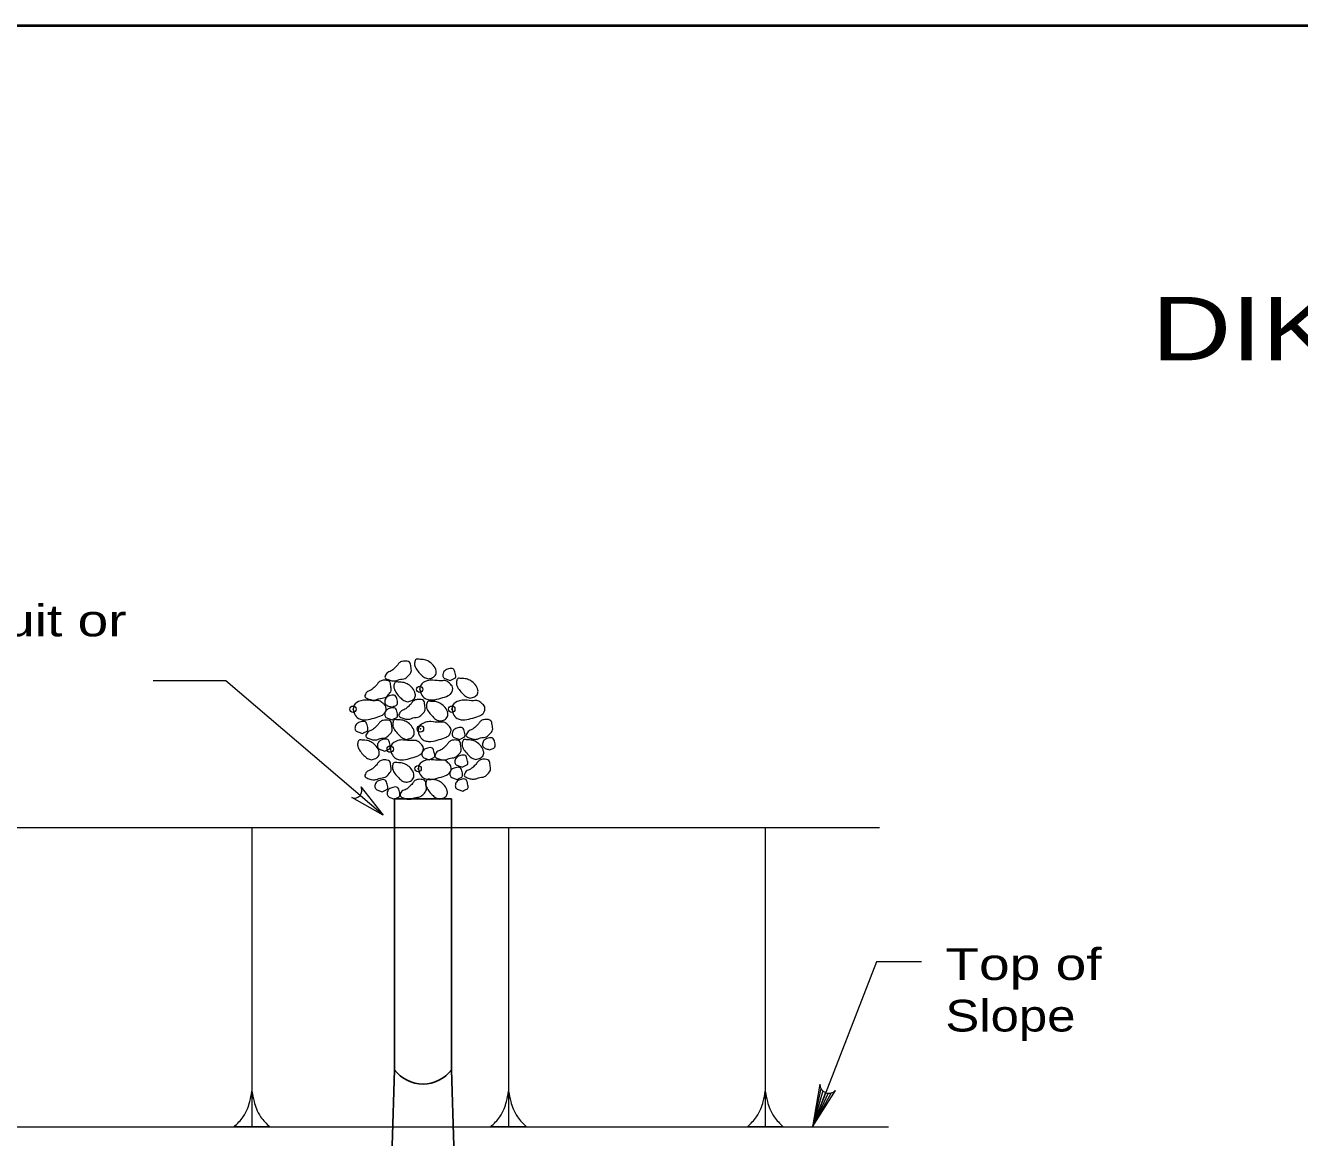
# Model space of a CAD drawing. Extents: x 1043.1 to 1101.1, y 672.4 to 716.4.
# Drawn here: x 1050.72 to 1057.15, y 688.26 to 693.9 of the extents above; entities that cross this region are included whole.
import ezdxf
from ezdxf.enums import TextEntityAlignment as Align

# ---------------------------------------------------------------- set-up
doc = ezdxf.new("R2010")
doc.units = 0
doc.header["$LTSCALE"] = 0.064
doc.header["$PDMODE"] = 32
doc.header["$PDSIZE"] = 0.032
doc.linetypes.add('LONG_DASHED', pattern=[7.5, 6, -1.5])
doc.layers.add('1', color=7, linetype='Continuous', lineweight=13)

msp = doc.modelspace()

# ---------------------------------------------------------------- linework, layer by layer
at = {"layer": '1', "lineweight": 25}
for p, q in [((1045.14425, 693.89508), (1076.64425, 693.89508)), ((1052.87325, 689.992), (1052.87325, 688.62467))]:
    msp.add_line(p, q, dxfattribs=at)
at = {"layer": '1', "lineweight": 40}
msp.add_line((1045.14425, 693.89508), (1076.64425, 693.89508), dxfattribs=at)
msp.add_line((1045.14425, 693.89508), (1076.64425, 693.89508), dxfattribs=at)
at = {"layer": '1'}
for p, q in [((1047.11617, 689.848), (1055.03217, 689.848)), ((1051.86575, 689.848), (1051.86575, 688.33692)), ((1053.16117, 689.848), (1053.16117, 688.33692)), ((1054.4565, 689.848), (1054.4565, 688.33692)), ((1054.73675, 688.53025), (1054.69375, 688.33692)), ((1054.74583, 688.51883), (1054.69375, 688.33692)), ((1054.76075, 688.50933), (1054.69375, 688.33692)), ((1054.78908, 688.5075), (1054.69375, 688.33692)), ((1054.77425, 688.50625), (1054.69375, 688.33692)), ((1054.75833, 688.50317), (1054.69475, 688.33942)), ((1047.11617, 688.33692), (1055.0785, 688.33692)), ((1051.95575, 688.33692), (1051.77583, 688.33692)), ((1053.25117, 688.33692), (1053.07117, 688.33692)), ((1054.5465, 688.33692), (1054.3665, 688.33692))]:
    msp.add_line(p, q, dxfattribs=at)
at = {"layer": '1', "linetype": 'LONG_DASHED', "lineweight": 25}
for p, q in [((1052.58533, 688.62467), (1052.55375, 687.54417)), ((1052.87325, 688.62467), (1052.905, 687.54417))]:
    msp.add_line(p, q, dxfattribs=at)
at = {"layer": '1'}
for points in [[(1052.528, 689.91042), (1051.73442, 690.58742), (1051.36792, 690.58742)], [(1052.41658, 690.05175), (1052.528, 689.91042), (1052.37075, 689.99808), (1052.37083, 689.99817)], [(1055.24533, 689.169), (1055.01717, 689.169), (1054.69375, 688.33692)], [(1054.73133, 688.55167), (1054.69375, 688.33692), (1054.811, 688.52067)]]:
    msp.add_lwpolyline(points, dxfattribs=at)
at = {"layer": '1', "lineweight": 25}
msp.add_lwpolyline([(1052.58533, 688.62467), (1052.58533, 689.992), (1052.87325, 689.992)], dxfattribs=at)
at = {"layer": '1'}
for centre, radius, start, end in [((1052.38283, 690.03431), 0.03811, 251.62064, 27.44677), ((1054.77748, 688.55222), 0.04613, 180.84579, 316.67192)]:
    msp.add_arc(centre, radius, start, end, dxfattribs=at)
at = {"layer": '1', "lineweight": 25}
msp.add_ellipse((1052.72935, 688.73267), major_axis=(-0.17991, 0), ratio=0.999895, start_param=0.6435011, end_param=2.4980916, dxfattribs=at)
at = {"layer": '1'}
for points in [[(1052.75592, 690.59767), (1052.73742, 690.60392), (1052.7185, 690.61925), (1052.69983, 690.64108), (1052.68783, 690.664), (1052.6875, 690.6815), (1052.69433, 690.69608), (1052.7095, 690.69667), (1052.73742, 690.69408), (1052.75917, 690.68467), (1052.78083, 690.66592), (1052.79517, 690.63775), (1052.79342, 690.61925), (1052.77792, 690.60392), (1052.75592, 690.59767)], [(1052.5715, 690.58792), (1052.55275, 690.594), (1052.53717, 690.60642), (1052.54017, 690.61558), (1052.54683, 690.62692), (1052.56833, 690.63725), (1052.58375, 690.64992), (1052.59933, 690.6655), (1052.60867, 690.67775), (1052.6245, 690.68592), (1052.64925, 690.68625), (1052.66183, 690.681), (1052.66792, 690.65925), (1052.67025, 690.63467), (1052.65492, 690.61292), (1052.63975, 690.60008), (1052.60867, 690.594), (1052.59317, 690.58792), (1052.5715, 690.58792)], [(1052.8665, 690.58917), (1052.848, 690.59525), (1052.83242, 690.60467), (1052.82925, 690.62017), (1052.8385, 690.63867), (1052.85775, 690.648), (1052.882, 690.64767), (1052.89133, 690.62625), (1052.89242, 690.60308), (1052.87917, 690.59525), (1052.8665, 690.58917)], [(1052.8665, 690.58917), (1052.848, 690.59525), (1052.83242, 690.60467), (1052.82925, 690.62017), (1052.8385, 690.63867), (1052.85775, 690.648), (1052.882, 690.64767), (1052.89133, 690.62625), (1052.89242, 690.60308), (1052.87917, 690.59525), (1052.8665, 690.58917)], [(1052.46975, 690.49125), (1052.45083, 690.49742), (1052.43525, 690.50975), (1052.43825, 690.51908), (1052.44492, 690.53042), (1052.46642, 690.54092), (1052.48192, 690.5535), (1052.4975, 690.56908), (1052.50692, 690.58125), (1052.52275, 690.5895), (1052.54742, 690.58975), (1052.56, 690.5845), (1052.56617, 690.56275), (1052.56833, 690.53817), (1052.55325, 690.51625), (1052.53792, 690.5035), (1052.50692, 690.49742), (1052.49142, 690.49125), (1052.46975, 690.49125)], [(1052.65117, 690.48208), (1052.63267, 690.48817), (1052.61383, 690.50375), (1052.59517, 690.5255), (1052.58317, 690.54842), (1052.58275, 690.56592), (1052.5895, 690.58058), (1052.60483, 690.58117), (1052.63267, 690.5785), (1052.65433, 690.56917), (1052.67617, 690.55025), (1052.69033, 690.52225), (1052.68875, 690.50375), (1052.67325, 690.48817), (1052.65117, 690.48208)], [(1052.75983, 690.4915), (1052.73942, 690.49867), (1052.71967, 690.52242), (1052.71675, 690.56317), (1052.75083, 690.58775), (1052.77875, 690.59075), (1052.82225, 690.58775), (1052.84392, 690.58775), (1052.86283, 690.57517), (1052.87833, 690.55625), (1052.8715, 690.52467), (1052.8565, 690.513), (1052.819, 690.50025), (1052.77875, 690.49125), (1052.75983, 690.4915)], [(1052.96683, 690.5005), (1052.94833, 690.50667), (1052.9295, 690.52225), (1052.91083, 690.544), (1052.89883, 690.56692), (1052.89842, 690.58442), (1052.90533, 690.59908), (1052.9205, 690.59967), (1052.94833, 690.597), (1052.97017, 690.58767), (1052.99183, 690.56875), (1053.00617, 690.54067), (1053.00442, 690.52225), (1052.98892, 690.50667), (1052.96683, 690.5005)], [(1052.57325, 690.45425), (1052.55492, 690.4605), (1052.53933, 690.46975), (1052.536, 690.48542), (1052.54542, 690.50392), (1052.56467, 690.51325), (1052.58875, 690.51292), (1052.59817, 690.4915), (1052.59917, 690.46825), (1052.58583, 690.4605), (1052.57325, 690.45425)], [(1052.42367, 690.391), (1052.40325, 690.39817), (1052.38342, 690.42167), (1052.3805, 690.4625), (1052.41467, 690.48708), (1052.44242, 690.49008), (1052.48617, 690.48708), (1052.50783, 690.48708), (1052.52675, 690.4745), (1052.54217, 690.45567), (1052.53542, 690.424), (1052.52042, 690.4125), (1052.48292, 690.39967), (1052.44242, 690.39067), (1052.42367, 690.391)], [(1052.57325, 690.39067), (1052.55492, 690.39692), (1052.53933, 690.40617), (1052.536, 690.42167), (1052.54542, 690.44017), (1052.56467, 690.4495), (1052.58875, 690.44917), (1052.59817, 690.42775), (1052.59917, 690.40467), (1052.58583, 690.39692), (1052.57325, 690.39067)], [(1052.64142, 690.3945), (1052.6225, 690.40058), (1052.60692, 690.41292), (1052.60992, 690.42217), (1052.61675, 690.4335), (1052.63817, 690.44392), (1052.65367, 690.4565), (1052.66925, 690.47208), (1052.67867, 690.48425), (1052.69442, 690.4925), (1052.71917, 690.49292), (1052.73175, 690.48758), (1052.73792, 690.46592), (1052.74017, 690.44125), (1052.72492, 690.41942), (1052.70975, 690.40667), (1052.67867, 690.40058), (1052.66317, 690.3945), (1052.64142, 690.3945)], [(1052.8155, 690.38508), (1052.797, 690.39117), (1052.77825, 690.40675), (1052.7595, 690.42842), (1052.7475, 690.45125), (1052.74717, 690.46892), (1052.75392, 690.4835), (1052.76925, 690.48408), (1052.797, 690.4815), (1052.81867, 690.47208), (1052.84033, 690.45325), (1052.85467, 690.42517), (1052.85292, 690.40675), (1052.8375, 690.39117), (1052.8155, 690.38508)], [(1052.92183, 690.391), (1052.90142, 690.39817), (1052.88167, 690.42167), (1052.87875, 690.4625), (1052.91283, 690.48708), (1052.94075, 690.49008), (1052.98433, 690.48708), (1053.00617, 690.48708), (1053.02492, 690.4745), (1053.04042, 690.45567), (1053.03375, 690.424), (1053.01875, 690.4125), (1052.98117, 690.39967), (1052.94075, 690.39067), (1052.92183, 690.391)], [(1052.4235, 690.32167), (1052.405, 690.32792), (1052.38942, 690.33717), (1052.38617, 690.35275), (1052.3955, 690.37125), (1052.41475, 690.38067), (1052.43892, 690.38025), (1052.44833, 690.35892), (1052.44942, 690.33567), (1052.43617, 690.32792), (1052.4235, 690.32167)], [(1052.47517, 690.29008), (1052.45625, 690.29617), (1052.44067, 690.3085), (1052.44367, 690.31792), (1052.45033, 690.32917), (1052.47183, 690.33958), (1052.48733, 690.35217), (1052.50292, 690.36775), (1052.51233, 690.38008), (1052.52817, 690.38817), (1052.55283, 690.38858), (1052.56542, 690.38325), (1052.5715, 690.36158), (1052.57383, 690.337), (1052.55867, 690.315), (1052.54333, 690.30225), (1052.51233, 690.29617), (1052.49683, 690.29008), (1052.47517, 690.29008)], [(1052.6455, 690.29192), (1052.627, 690.298), (1052.60817, 690.31358), (1052.58942, 690.33525), (1052.57742, 690.35817), (1052.57717, 690.37567), (1052.58392, 690.39042), (1052.59917, 690.391), (1052.627, 690.38825), (1052.64875, 690.379), (1052.67042, 690.36008), (1052.68475, 690.33208), (1052.683, 690.31358), (1052.6675, 690.298), (1052.6455, 690.29192)], [(1052.75075, 690.28225), (1052.73033, 690.2895), (1052.7105, 690.31308), (1052.70767, 690.35392), (1052.74175, 690.3785), (1052.7695, 690.3815), (1052.81325, 690.3785), (1052.83483, 690.3785), (1052.85375, 690.36592), (1052.86917, 690.34708), (1052.86242, 690.31542), (1052.84742, 690.30367), (1052.81, 690.291), (1052.7695, 690.282), (1052.75075, 690.28225)], [(1052.98167, 690.29325), (1052.96275, 690.29942), (1052.94717, 690.31175), (1052.95017, 690.32108), (1052.95692, 690.33242), (1052.97833, 690.34292), (1052.99383, 690.3555), (1053.00942, 690.37108), (1053.01883, 690.38325), (1053.03467, 690.3915), (1053.05933, 690.39175), (1053.07183, 690.3865), (1053.07792, 690.36475), (1053.08025, 690.34017), (1053.065, 690.31825), (1053.04992, 690.3055), (1053.01883, 690.29942), (1053.00333, 690.29325), (1052.98167, 690.29325)], [(1052.91342, 690.29142), (1052.89492, 690.2975), (1052.87933, 690.30692), (1052.87617, 690.3225), (1052.8855, 690.34092), (1052.90475, 690.35025), (1052.92892, 690.34992), (1052.93833, 690.32858), (1052.93933, 690.30525), (1052.926, 690.2975), (1052.91342, 690.29142)], [(1052.46833, 690.1895), (1052.44992, 690.19558), (1052.431, 690.21117), (1052.41233, 690.23275), (1052.40033, 690.25567), (1052.39992, 690.27325), (1052.40683, 690.28792), (1052.422, 690.2885), (1052.44992, 690.28592), (1052.47167, 690.2765), (1052.49333, 690.25767), (1052.50767, 690.22958), (1052.50592, 690.21117), (1052.49042, 690.19558), (1052.46833, 690.1895)], [(1052.5365, 690.2325), (1052.518, 690.23858), (1052.50242, 690.24792), (1052.49925, 690.2635), (1052.5085, 690.282), (1052.52775, 690.29142), (1052.552, 690.291), (1052.56133, 690.26967), (1052.56242, 690.24642), (1052.54917, 690.23858), (1052.5365, 690.2325)], [(1052.611, 690.18967), (1052.59067, 690.19692), (1052.57083, 690.2205), (1052.56817, 690.26125), (1052.602, 690.28592), (1052.62992, 690.28892), (1052.6735, 690.28592), (1052.69533, 690.28592), (1052.71417, 690.27325), (1052.72967, 690.25442), (1052.72292, 690.22267), (1052.70792, 690.21117), (1052.67033, 690.1985), (1052.62992, 690.1895), (1052.611, 690.18967)], [(1052.76083, 690.1895), (1052.74233, 690.19558), (1052.72675, 690.20492), (1052.7235, 690.2205), (1052.73283, 690.23892), (1052.752, 690.24825), (1052.77633, 690.24792), (1052.78567, 690.22658), (1052.78675, 690.20342), (1052.77342, 690.19558), (1052.76083, 690.1895)], [(1052.82325, 690.1895), (1052.8045, 690.19558), (1052.78892, 690.208), (1052.79192, 690.21717), (1052.79867, 690.2285), (1052.81992, 690.23892), (1052.83542, 690.2515), (1052.851, 690.26708), (1052.86042, 690.27942), (1052.87625, 690.2875), (1052.90092, 690.28792), (1052.9135, 690.28258), (1052.91975, 690.26092), (1052.92192, 690.23625), (1052.90675, 690.2145), (1052.8915, 690.20167), (1052.86042, 690.19558), (1052.84492, 690.1895), (1052.82325, 690.1895)], [(1052.9955, 690.19125), (1052.977, 690.19742), (1052.95825, 690.213), (1052.9395, 690.23458), (1052.9275, 690.2575), (1052.92717, 690.27508), (1052.93392, 690.28967), (1052.94925, 690.29025), (1052.977, 690.28767), (1052.99875, 690.27825), (1053.0205, 690.2595), (1053.03475, 690.23142), (1053.03317, 690.213), (1053.01767, 690.19742), (1052.9955, 690.19125)], [(1053.06633, 690.23908), (1053.04792, 690.24517), (1053.03233, 690.2545), (1053.02917, 690.27008), (1053.0385, 690.28858), (1053.0575, 690.298), (1053.08183, 690.29758), (1053.09117, 690.27625), (1053.09225, 690.253), (1053.07892, 690.24517), (1053.06633, 690.23908)], [(1052.46975, 690.08892), (1052.45083, 690.09508), (1052.43525, 690.10742), (1052.43825, 690.11675), (1052.44492, 690.12808), (1052.46642, 690.1385), (1052.48192, 690.15108), (1052.4975, 690.16667), (1052.50692, 690.17892), (1052.52275, 690.18708), (1052.54742, 690.1875), (1052.56, 690.18217), (1052.56617, 690.1605), (1052.56833, 690.13592), (1052.55325, 690.11392), (1052.53792, 690.10117), (1052.50692, 690.09508), (1052.49142, 690.08892), (1052.46975, 690.08892)], [(1052.75183, 690.0905), (1052.73142, 690.09767), (1052.71167, 690.12125), (1052.70875, 690.16208), (1052.74283, 690.18667), (1052.77067, 690.18967), (1052.81425, 690.18667), (1052.83592, 690.18667), (1052.85475, 690.17408), (1052.87025, 690.15525), (1052.8635, 690.12358), (1052.8485, 690.112), (1052.81092, 690.09925), (1052.77067, 690.09025), (1052.75183, 690.0905)], [(1052.92733, 690.15208), (1052.90892, 690.15817), (1052.89333, 690.1675), (1052.89, 690.18308), (1052.89942, 690.20158), (1052.91867, 690.211), (1052.94283, 690.21058), (1052.95225, 690.18925), (1052.95333, 690.166), (1052.93992, 690.15817), (1052.92733, 690.15208)], [(1052.97142, 690.09217), (1052.9525, 690.09825), (1052.93692, 690.11067), (1052.93992, 690.12), (1052.94675, 690.13125), (1052.96817, 690.14167), (1052.98367, 690.15425), (1052.99925, 690.16992), (1053.00867, 690.18217), (1053.02442, 690.19025), (1053.04917, 690.19067), (1053.06167, 690.18542), (1053.06775, 690.16367), (1053.07, 690.13908), (1053.05492, 690.11708), (1053.03975, 690.10442), (1053.00867, 690.09825), (1052.99317, 690.09217), (1052.97142, 690.09217)], [(1052.64383, 690.07592), (1052.62533, 690.082), (1052.6065, 690.09758), (1052.58775, 690.11925), (1052.57592, 690.14217), (1052.57542, 690.15967), (1052.58233, 690.17442), (1052.5975, 690.175), (1052.62533, 690.17225), (1052.647, 690.163), (1052.66875, 690.14408), (1052.683, 690.11608), (1052.68133, 690.09758), (1052.66592, 690.082), (1052.64383, 690.07592)], [(1052.90142, 690.09025), (1052.88292, 690.09642), (1052.86733, 690.10567), (1052.86417, 690.12125), (1052.8735, 690.13975), (1052.89275, 690.14917), (1052.91692, 690.14875), (1052.92633, 690.1275), (1052.92733, 690.10417), (1052.914, 690.09642), (1052.90142, 690.09025)], [(1052.52342, 690.02808), (1052.50492, 690.03417), (1052.48933, 690.04358), (1052.48617, 690.05917), (1052.4955, 690.07767), (1052.51475, 690.087), (1052.53892, 690.08667), (1052.54833, 690.06525), (1052.54933, 690.042), (1052.536, 690.03417), (1052.52342, 690.02808)], [(1052.58525, 689.991), (1052.56675, 689.99708), (1052.55133, 690.0065), (1052.548, 690.022), (1052.55742, 690.0405), (1052.5765, 690.04975), (1052.60075, 690.0495), (1052.61017, 690.02808), (1052.61117, 690.00492), (1052.59783, 689.99708), (1052.58525, 689.991)], [(1052.64775, 689.991), (1052.62892, 689.99708), (1052.61333, 690.0095), (1052.61633, 690.01867), (1052.623, 690.03), (1052.6445, 690.0405), (1052.66, 690.05308), (1052.67567, 690.06867), (1052.68492, 690.08092), (1052.70083, 690.08908), (1052.7255, 690.08942), (1052.73817, 690.08408), (1052.74425, 690.06242), (1052.7465, 690.03775), (1052.73133, 690.01592), (1052.716, 690.00325), (1052.68492, 689.99708), (1052.6695, 689.991), (1052.64775, 689.991)], [(1052.81267, 689.991), (1052.79417, 689.99708), (1052.77533, 690.01267), (1052.75667, 690.03425), (1052.74467, 690.05725), (1052.74425, 690.07475), (1052.75117, 690.08942), (1052.76633, 690.09), (1052.79417, 690.08742), (1052.81575, 690.078), (1052.8375, 690.05917), (1052.85175, 690.03108), (1052.85017, 690.01267), (1052.83467, 689.99708), (1052.81267, 689.991)], [(1052.92967, 690.03117), (1052.91117, 690.03725), (1052.8955, 690.04667), (1052.89233, 690.06225), (1052.90175, 690.08075), (1052.92092, 690.09008), (1052.94517, 690.08975), (1052.9545, 690.06842), (1052.9555, 690.04508), (1052.94225, 690.03725), (1052.92967, 690.03117)], [(1051.77583, 688.33692), (1051.82175, 688.3875), (1051.84292, 688.42708), (1051.85492, 688.4645), (1051.86575, 688.51675)], [(1051.86575, 688.51675), (1051.8765, 688.4645), (1051.88867, 688.42708), (1051.90992, 688.3875), (1051.95575, 688.33692)], [(1053.07117, 688.33692), (1053.11692, 688.3875), (1053.13825, 688.42708), (1053.15033, 688.4645), (1053.16117, 688.51675)], [(1053.16117, 688.51675), (1053.17192, 688.4645), (1053.184, 688.42708), (1053.20533, 688.3875), (1053.25117, 688.33692)], [(1054.3665, 688.33692), (1054.41225, 688.3875), (1054.43358, 688.42708), (1054.44567, 688.4645), (1054.4565, 688.51675)], [(1054.4565, 688.51675), (1054.46725, 688.4645), (1054.47933, 688.42708), (1054.50067, 688.3875), (1054.5465, 688.33692)]]:
    msp.add_spline(points, degree=3, dxfattribs=at)
for p in [(1052.71242, 690.54492), (1052.37625, 690.44425), (1052.87442, 690.44425), (1052.71642, 690.345), (1052.56375, 690.243), (1052.70442, 690.14392)]:
    msp.add_point(p, dxfattribs=at)

# ---------------------------------------------------------------- texts
at = {"layer": '1', "width": 1.3}
msp.add_text('DIKES AND SLOPE PROTECTION', height=0.32, dxfattribs=at).set_placement((1060.81029, 692.20542), align=Align.CENTER)
at = {"layer": '1'}
for s, width, p in [('Temporary conduit or', 1.3, (1048.59017, 690.81208)), ('Top of', 1.3, (1055.36483, 689.07775)), ('Slope', 1.2, (1055.36483, 688.81775))]:
    msp.add_text(s, height=0.16, dxfattribs=dict(at, width=width)).set_placement(p)

doc.saveas('drawing.dxf')
